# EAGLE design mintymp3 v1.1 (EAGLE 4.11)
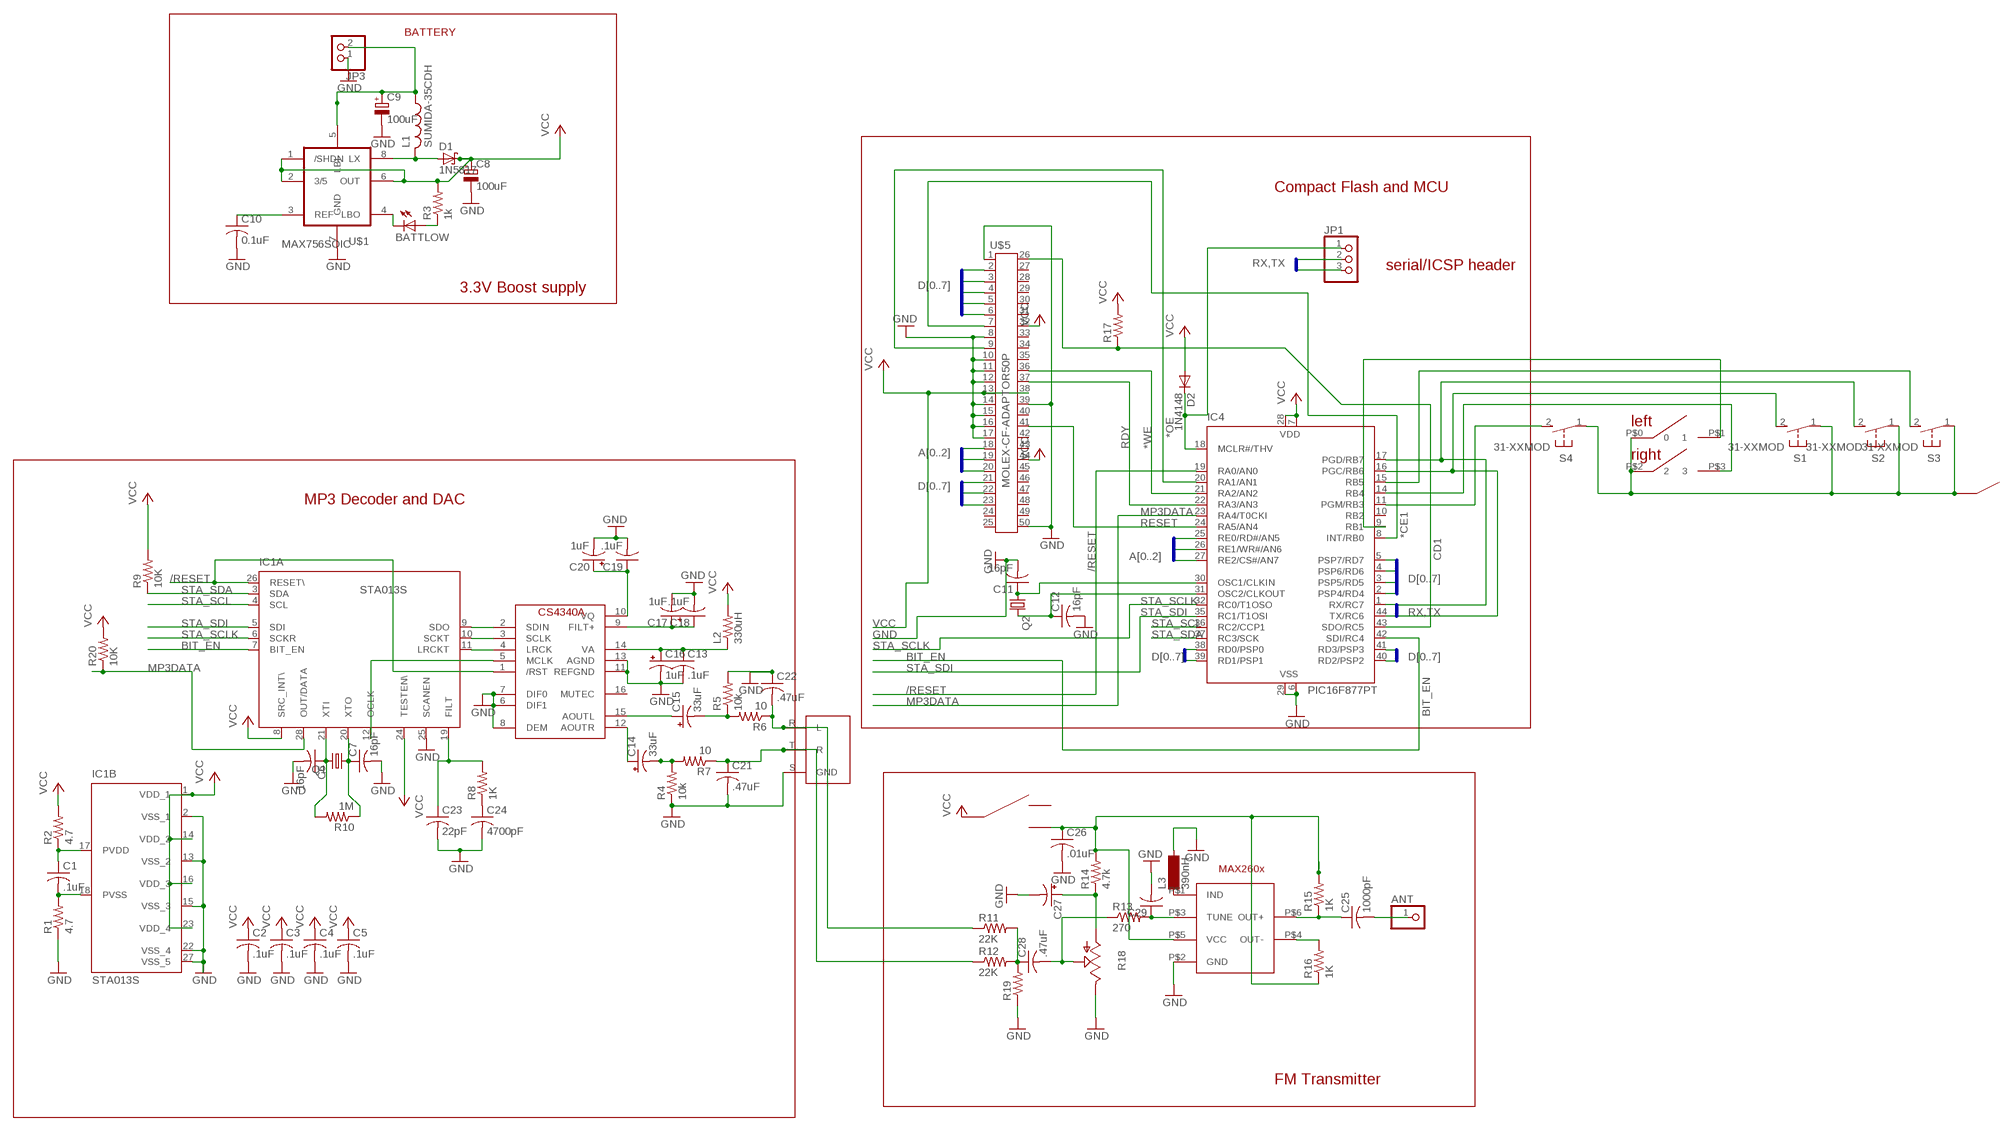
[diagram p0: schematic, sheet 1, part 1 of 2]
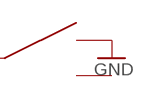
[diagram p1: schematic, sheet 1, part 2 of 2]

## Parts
ANT  PINHD-1X1  [1X01]
BATTLOW  LED3MM  [LED3MM]
C1  .1uF  C-USC1206  [C1206]
C2  .1uF  C-USC1206  [C1206]
C3  .1uF  C-USC1206  [C1206]
C4  .1uF  C-USC1206  [C1206]
C5  .1uF  C-USC1206  [C1206]
C6  16pF  C-USC1206  [C1206]
C7  16pF  C-USC1206  [C1206]
C8  100uF  CPOL-EUD  [PANASONIC_D]
C9  100uF  CPOL-EUD  [PANASONIC_D]
C10  0.1uF  C-USC1206  [C1206]
C11  16pF  C-USC1206  [C1206]
C12  16pF  C-USC1206  [C1206]
C13  .1uF  C-USC1206  [C1206]
C14  33uF  CPOL-USB  [PANASONIC_B]
C15  33uF  CPOL-USB  [PANASONIC_B]
C16  1uF  CPOL-USA  [PANASONIC_A]
C17  1uF  CPOL-USA  [PANASONIC_A]
C18  .1uF  C-USC1206  [C1206]
C19  .1uF  C-USC1206  [C1206]
C20  1uF  CPOL-USA  [PANASONIC_A]
C21  .47uF  C-USC1206  [C1206]
C22  .47uF  C-USC1206  [C1206]
C23  22pF  C-USC1206  [C1206]
C24  4700pF  C-USC1206  [C1206]
C25  1000pF  C-USC1206  [C1206]
C26  .01uF  C-USC1206  [C1206]
C27  CPOL-USB  [PANASONIC_B]
C28  .47uF  C-USC1206  [C1206]
C29  C-USC1206  [C1206]
D1  1N5817  SCHOTTKY-DIODEDO35-7  [DO35-7]
D2  1N4148  [DO35-10]
FM_SWITCH  SLIDE_SW  [SLIDESWITCH]
HEADPHONE  STEREOJACKSMDMOD  [SJ-3523-MODIFIED]
IC1  STA013S  [SO28W]
IC4  PIC16F877PT  [TQFP44]
JP1  PINHD-1X3  [1X03]
JP3  PINHD-1X2  [1X02]
L1  SUMIDA-35CDH  [CDH53]
L2  330uH  R-US_R1210  [R1210]
L3  390nH  SM-1206  [SM-1206]
Q1  CRYTALHC49UP  [HC49UP]
Q2  CRYTALHC49UP  [HC49UP]
R1  4.7  R-US_R1206  [R1206]
R2  4.7  R-US_R1206  [R1206]
R3  1k  R-US_R1206  [R1206]
R4  10k  R-US_R1206  [R1206]
R5  10k  R-US_R1206  [R1206]
R6  10  R-US_R1206  [R1206]
R7  10  R-US_R1206  [R1206]
R8  1K  R-US_R1206  [R1206]
R9  10K  R-US_R1206  [R1206]
R10  1M  R-US_R1206  [R1206]
R11  22K  R-US_R1206  [R1206]
R12  22K  R-US_R1206  [R1206]
R13  270  R-US_R1206  [R1206]
R14  4.7k  R-US_R1206  [R1206]
R15  1K  R-US_R1206  [R1206]
R16  1K  R-US_R1206  [R1206]
R17  R-US_R1206  [R1206]
R18  TRIM_US-ECP10P  [ECP10P]
R19  R-US_R1206  [R1206]
R20  10K  R-US_R1206  [R1206]
S1  31-XXMOD  [B3F-31XX-MODIFIED]
S2  31-XXMOD  [B3F-31XX-MODIFIED]
S3  31-XXMOD  [B3F-31XX-MODIFIED]
S4  31-XXMOD  [B3F-31XX-MODIFIED]
U$1  MAX756SOIC  [SO08]
U$2  SLIDE_SW  [SLIDESWITCH]
U$3  TPC_SWITCH  [TPC_SCAN]
U$4  CS4340A  [SO16]
U$5  MOLEX-CF-ADAPTOR50P  [COMPACTFLASH]
U$9  MAX260X  [SOT23-6]

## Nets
*CE1: IC4.8(INT/RB0) U$5.7
*OE: IC4.20(RA1/AN1) U$5.9
*WE: IC4.21(RA2/AN2) U$5.36
/RESET: IC1.26(A:RESET\) IC4.19(RA0/AN0) U$4.1(/RST)
A0: IC4.25(RE0/RD#/AN5) U$5.20
A1: IC4.26(RE1/WR#/AN6) U$5.19
A2: IC4.27(RE2/CS#/AN7) U$5.18
ANTENNA: ANT.1 C25.2
BIT_EN: IC1.7(A:BIT_EN) IC4.42(SDI/RC4)
BUTTON1: IC4.11(PGM/RB3) S4.2(S)
CD1: IC4.43(SDO/RC5) R17.1 U$5.26
D0: IC4.38(RD0/PSP0) U$5.21
D1: IC4.39(RD1/PSP1) U$5.22
D2: IC4.40(RD2/PSP2) U$5.23
D3: IC4.41(RD3/PSP3) U$5.2
D4: IC4.2(PSP4/RD4) U$5.3
D5: IC4.3(PSP5/RD5) U$5.4
D6: IC4.4(PSP6/RD6) U$5.5
D7: IC4.5(PSP7/RD7) U$5.6
GND: C2.2 C3.2 C4.2 C5.2 C6.2 C7.2 C8.- C9.- C10.2 C11.2 C12.2 C13.2 C16.- C17.- C18.2 C19.2 C20.- C21.2 C22.1 C23.2 C24.2 C26.2 C27.- C29.2 HEADPHONE.S(GND) IC1.2(B:VSS_1) IC1.13(B:VSS_2) IC1.15(B:VSS_3) IC1.22(B:VSS_4) IC1.25(A:SCANEN) IC1.27(B:VSS_5) IC4.6(VSS) IC4.29(VSS) JP3.1 L3.2 R1.1 R4.1 R5.2 R18.E R19.1 U$1.7(GND) U$2.P$1 U$4.6(DIF1) U$4.7(DIF0) U$4.8(DEM) U$4.11(REFGND) U$4.13(AGND) U$5.1 U$5.8 U$5.10 U$5.11 U$5.12 U$5.14 U$5.15 U$5.16 U$5.17 U$5.39 U$5.50 U$9.P$2(GND)
MCLR: D2.C IC4.18(MCLR#/THV) JP1.1
MP3DATA: IC1.28(A:OUT/DATA) IC4.23(RA4/T0CKI) R20.1
N$2: C26.1 FM_SWITCH.P$3 R14.2 R15.2 R16.1 U$9.P$5(VCC)
N$3: C6.1 IC1.21(A:XTI) Q1.2 R10.2
N$4: C7.1 IC1.20(A:XTO) Q1.1 R10.1
N$5: IC4.14(RB4) U$3.P$3
N$6: C1.1 IC1.17(B:PVDD) R2.1
N$7: C1.2 IC1.18(B:PVSS) R1.2
N$8: C9.+ JP3.2 L1.P$1 U$1.5(LBI)
N$9: D1.A L1.P$2 U$1.8(LX)
N$10: IC1.9(A:SDO) U$4.2(SDIN)
N$11: IC1.10(A:SCKT) U$4.3(SCLK)
N$12: IC1.11(A:LRCKT) U$4.4(LRCK)
N$13: IC1.12(A:OCLK) U$4.5(MCLK)
N$14: IC4.9(RB1) U$3.P$1
N$16: IC4.15(RB5) S3.2(S)
N$17: C15.+ U$4.15(AOUTL)
N$18: C10.1 U$1.3(REF)
N$19: BATTLOW.A R3.1
N$20: BATTLOW.K(C) U$1.4(LBO)
N$21: C13.1 C16.+ L2.1 U$4.14(VA)
N$22: C11.1 IC4.30(OSC1/CLKIN) Q2.1
N$23: C12.1 IC4.31(OSC2/CLKOUT) Q2.2
N$24: C14.+ U$4.12(AOUTR)
N$25: C14.- R4.2 R7.2
N$26: C15.- R5.1 R6.2
N$28: C22.2 HEADPHONE.R(L) R6.1 R11.1
N$29: C17.+ C18.1 U$4.9(FILT+)
N$30: C19.1 C20.+ U$4.10(VQ)
N$31: C29.1 R13.2 U$9.P$3(TUNE)
N$32: C24.1 R8.1
N$33: C23.1 IC1.19(A:FILT) R8.2
N$35: C25.1 R15.1 U$9.P$6(OUT+)
N$36: R16.2 U$9.P$4(OUT-)
N$37: C21.1 HEADPHONE.T(R) R7.1 R12.1
N$38: C28.1 R11.2 R12.2 R19.2
N$39: C27.+ R14.1 R18.A
N$40: C28.2 R13.1 R18.S
N$42: L3.1 U$9.P$1(IND)
N$43: S1.1(P) S2.1(P) S3.1(P) S4.1(P) U$2.P$2 U$3.P$0 U$3.P$2
RDY: IC4.22(RA3/AN3) U$5.37
RESET: IC4.24(RA5/AN4) U$5.41
RX: IC4.1(RX/RC7) IC4.17(PGD/RB7) JP1.2 S2.2(S)
STA_SCL: IC1.4(A:SCL) IC4.36(RC2/CCP1)
STA_SCLK: IC1.6(A:SCKR) IC4.32(RC0/T1OSO)
STA_SDA: IC1.3(A:SDA) IC4.37(RC3/SCK) R9.1
STA_SDI: IC1.5(A:SDI) IC4.35(RC1/T1OSI)
TX: IC4.16(PGC/RB6) IC4.44(TX/RC6) JP1.3 S1.2(S)
VCC: C2.1 C3.1 C4.1 C5.1 C8.+ D1.C D2.A FM_SWITCH.P$2 IC1.1(B:VDD_1) IC1.8(A:SRC_INT\) IC1.14(B:VDD_2) IC1.16(B:VDD_3) IC1.23(B:VDD_4) IC1.24(A:TESTEN\) IC4.7(VDD) IC4.28(VDD) L2.2 R2.2 R3.2 R9.2 R17.2 R20.2 U$1.1(/SHDN) U$1.2(3/5) U$1.6(OUT) U$5.13 U$5.32 U$5.38 U$5.44
Unconnected: FM_SWITCH.P$1 IC4.10(RB2) U$2.P$3 U$4.16(MUTEC) U$5.24 U$5.25 U$5.27 U$5.28 U$5.29 U$5.30 U$5.31 U$5.33 U$5.34 U$5.35 U$5.40 U$5.42 U$5.43 U$5.45 U$5.46 U$5.47 U$5.48 U$5.49

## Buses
D[0..7]
A[0..2]
RX,TX

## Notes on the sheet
- BATTERY
- Compact Flash and MCU
- serial/ICSP header
- 3.3V Boost supply
- MP3 Decoder and DAC
- FM Transmitter

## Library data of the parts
ANT = pinhead:PINHD-1X1: PIN HEADER
BATTLOW = led:LED: LED
C1-C7 C10-C13 C18 C19 C21-C26 C28 C29 = rcl:C-US: CAPACITOR, American symbol
C8 C9 = rcl:CPOL-EU: POLARIZED CAPACITOR, European symbol
C14-C17 C20 C27 = rcl:CPOL-US: POLARIZED CAPACITOR, American symbol
D1 = diode:SCHOTTKY-DIODE: Schottky Diode
D2 = diode:1N4148: DIODE
FM_SWITCH U$2 = mp3:SLIDE_SW
HEADPHONE = mp3:STEREOJACK: CUI SJ-3533-N
IC1 = st-microelectronics:STA013S: MP3 AUDIO DECODER
IC4 = microchip:PIC16F87*: MICROCONTROLLER
JP1 = pinhead:PINHD-1X3: PIN HEADER
JP3 = pinhead:PINHD-1X2: PIN HEADER
L1 = mp3:SUMIDA-35CDH
L2 R1-R17 R19 R20 = rcl:R-US_: RESISTOR, American symbol
L3 = inductor-neosid:SM-1206: INDUCTOR
Q1 Q2 = crystal:CRYTAL: CRYSTAL
R18 = pot:TRIM_US-: POTENTIOMETER
S1-S4 = mp3:31-XX: OMRON SWITCH
U$1 = mp3:MAX756
U$3 = mp3:TPC_SWITCH
U$4 = mp3:CS4340A
U$5 = mp3:MOLEX-CF-ADAPTOR
U$9 = mp3:MAX260X

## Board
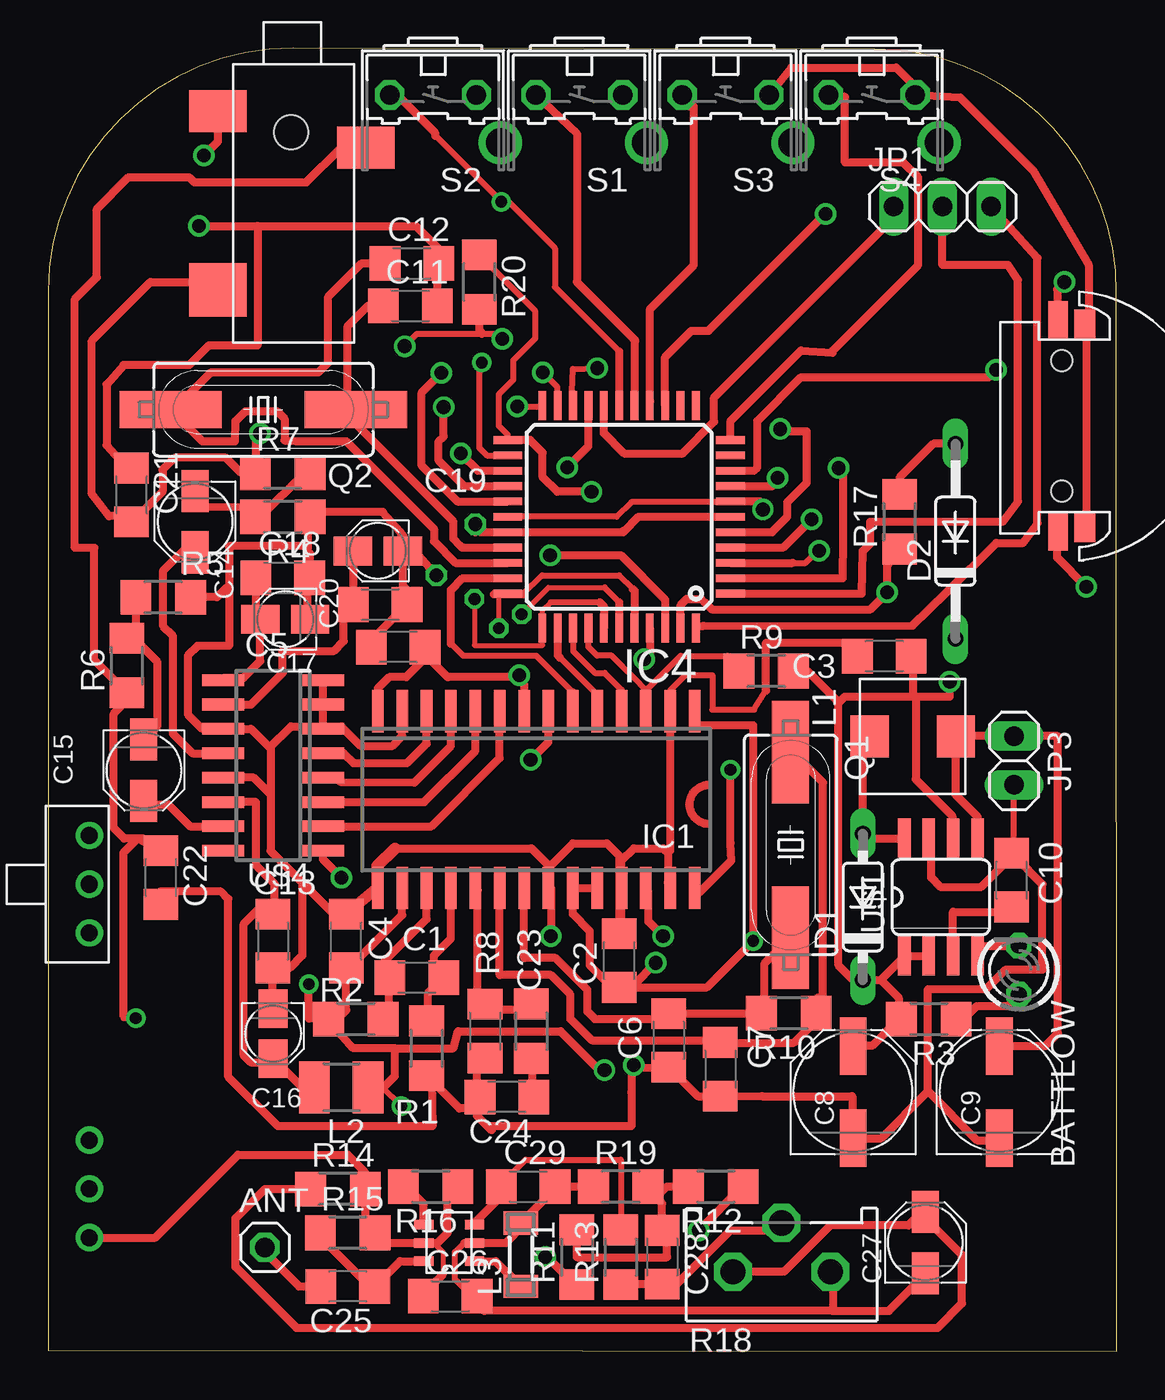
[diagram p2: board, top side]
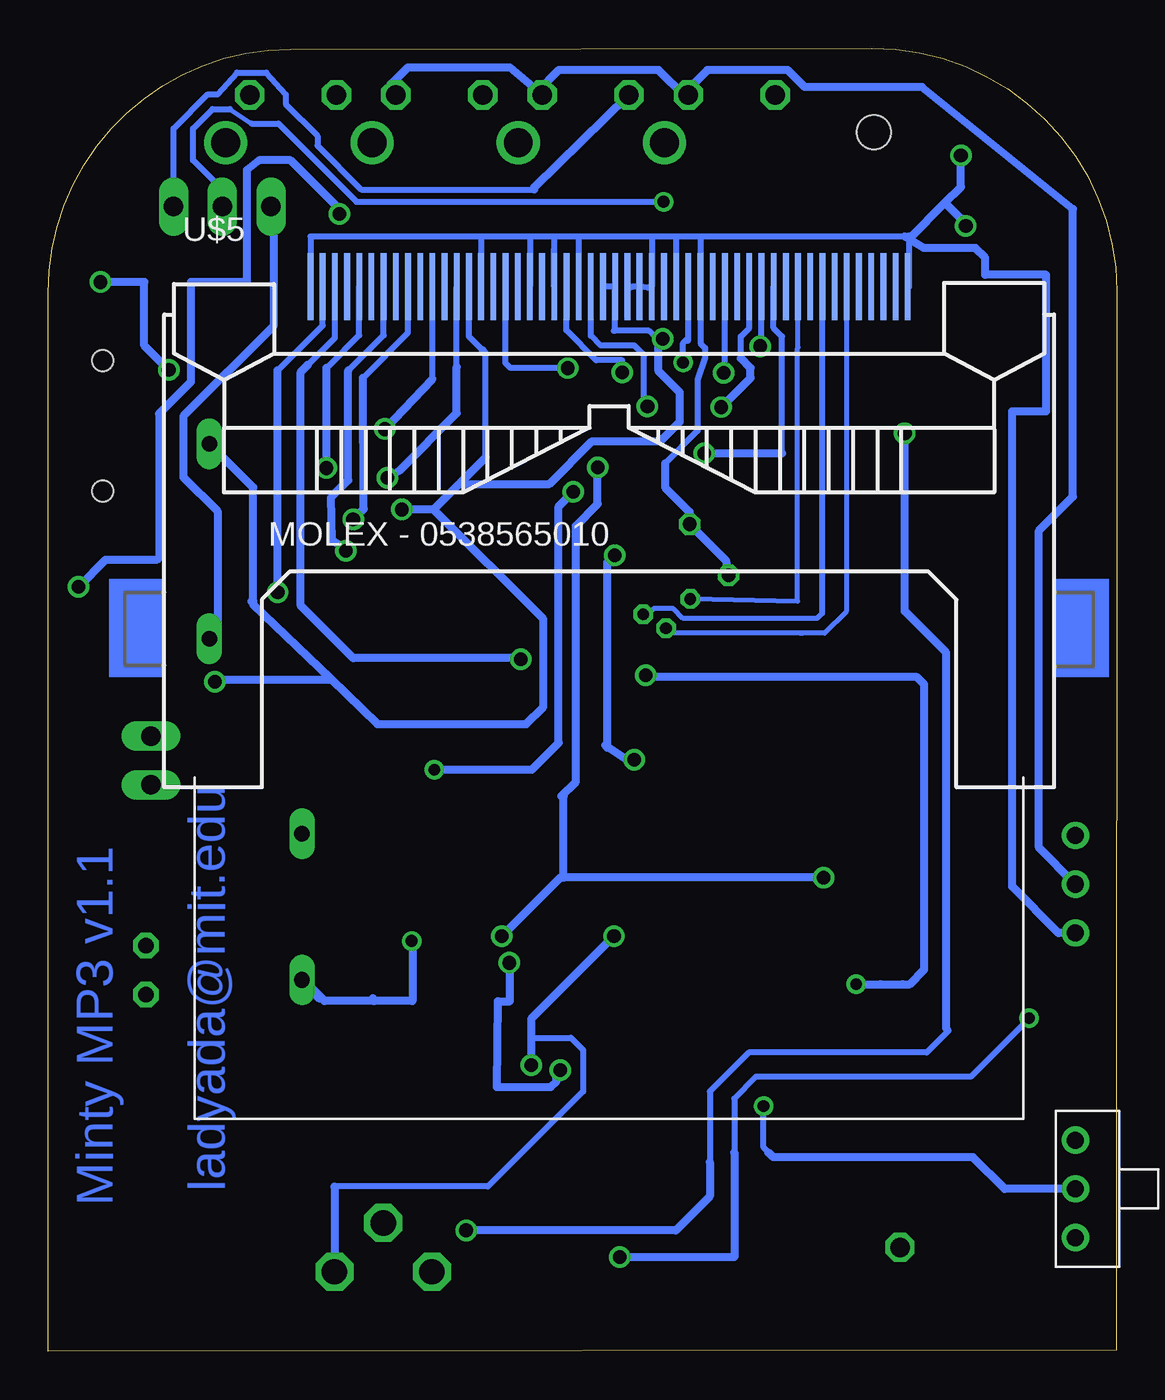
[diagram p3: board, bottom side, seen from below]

Size 55.69 x 67.92 mm. Coordinates in mm from the lower left corner, seen from the top.
Outline: 0.02,0.05 55.69,0 55.67,55.15 arc90 43.06,67.86 12.76,67.91 arc90 0,55.24 0.02,0.05
Copper layers (1*16): Top 0.035mm / dielectric 1.5mm / Bottom 0.035mm
Design rules "default": minimum track width 10mil, minimum drill 24mil, track to track 10mil, track to pad 10mil, pad to pad 10mil, via to via 10mil, smd to smd 8mil, copper to edge 20mil, drill to drill 8mil, minimum pad ring 10mil, minimum via ring 8mil, stop-mask expansion 4mil, vias tented up to drill 0mil, thermal gap 10mil

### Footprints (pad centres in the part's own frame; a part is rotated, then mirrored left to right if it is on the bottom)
1X01 = drill 1.016 octagon: 1 0,0
LED3MM = drill 0.813 octagon: A -1.27,0; K 1.27,0
C1206 = smd 1.6 x 1.8: 1 -1.4,0; 2 1.4,0
PANASONIC_D = smd 3 x 1.4: + 2.4,0; - -2.4,0
PANASONIC_B = smd 2.2 x 1.4: + 1.6,0; - -1.6,0
PANASONIC_A = smd 2 x 1.5: + 1.3,0; - -1.3,0
DO35-7 = drill 0.813 long: A 3.81,0; C -3.81,0
DO35-10 = drill 0.813 long: A 5.08,0; C -5.08,0
SLIDESWITCH = drill 0.889 pad 1.422 round: P$1 -2.54,1.016; P$2 0,1.016; P$3 2.54,1.016
SJ-3523-MODIFIED = smd 2.2 x 3: R -3.27,3.82; S -5.17,-3.88 | smd 2.8 x 3: T 4.13,-3.88 | hole 1.778: -4.07,-0.08
SO28W = smd 0.6 x 2.2: 1 -8.255,-4.6; 2 -6.985,-4.6; 3 -5.715,-4.6; 4 -4.445,-4.6; 5 -3.175,-4.6; 6 -1.905,-4.6; 7 -0.635,-4.6; 8 0.635,-4.6; 9 1.905,-4.6; 10 3.175,-4.6; 11 4.445,-4.6; 12 5.715,-4.6; 13 6.985,-4.6; 14 8.255,-4.6; 15 8.255,4.6; 16 6.985,4.6; 17 5.715,4.6; 18 4.445,4.6; 19 3.175,4.6; 20 1.905,4.6; 21 0.635,4.6; 22 -0.635,4.6; 23 -1.905,4.6; 24 -3.175,4.6; 25 -4.445,4.6; 26 -5.715,4.6; 27 -6.985,4.6; 28 -8.255,4.6
TQFP44 = smd 1.5 x 0.4: 1 -5.8,4; 2 -5.8,3.2; 3 -5.8,2.4; 4 -5.8,1.6; 5 -5.8,0.8; 6 -5.8,0; 7 -5.8,-0.8; 8 -5.8,-1.6; 9 -5.8,-2.4; 10 -5.8,-3.2; 11 -5.8,-4; 23 5.8,-4; 24 5.8,-3.2; 25 5.8,-2.4; 26 5.8,-1.6; 27 5.8,-0.8; 28 5.8,0; 29 5.8,0.8; 30 5.8,1.6; 31 5.8,2.4; 32 5.8,3.2; 33 5.8,4 | smd 0.4 x 1.5: 12 -4,-5.8; 13 -3.2,-5.8; 14 -2.4,-5.8; 15 -1.6,-5.8; 16 -0.8,-5.8; 17 0,-5.8; 18 0.8,-5.8; 19 1.6,-5.8; 20 2.4,-5.8; 21 3.2,-5.8; 22 4,-5.8; 34 4,5.8; 35 3.2,5.8; 36 2.4,5.8; 37 1.6,5.8; 38 0.8,5.8; 39 0,5.8; 40 -0.8,5.8; 41 -1.6,5.8; 42 -2.4,5.8; 43 -3.2,5.8; 44 -4,5.8
1X03 = drill 1.016 long: 1 -2.54,0; 2 0,0; 3 2.54,0
1X02 = drill 1.016 long: 1 -1.27,0; 2 1.27,0
CDH53 = smd 2.2 x 2: P$1 1,1; P$2 1,5.5
R1210 = smd 1.6 x 2.7: 1 -1.4,0; 2 1.4,0
SM-1206 = smd 1.2 x 1.8: 1 -1.65,0; 2 1.65,0
HC49UP = smd 5.334 x 1.93: 1 -4.826,0; 2 4.826,0
R1206 = smd 1.6 x 1.803: 1 -1.422,0; 2 1.422,0
ECP10P = drill 1.321 octagon: A -2.54,0; E 2.54,0; S 0,2.54
B3F-31XX-MODIFIED = drill 1.016 octagon: 1 -2.261,-1.245; 2 2.261,-1.245 | drill 1.499 pad 2.159 round: 3 -3.505,1.245
SO08 = smd 0.66 x 2.032: 1 -1.905,-3.073; 2 -0.635,-3.073; 3 0.635,-3.073; 4 1.905,-3.073; 5 1.905,3.073; 6 0.635,3.073; 7 -0.635,3.073; 8 -1.905,3.073
TPC_SCAN = smd 1.5 x 1.1: P$0 -5.3,1.2; P$2 5.3,1.2 | smd 2 x 1: P$1 -5.5,-0.2; P$3 5.5,-0.2 | hole 1.1: -3.4,0; 3.4,0
SO16 = smd 0.6 x 2.2: 1 -4.445,-2.6; 2 -3.175,-2.6; 3 -1.905,-2.6; 4 -0.635,-2.6; 5 0.635,-2.6; 6 1.905,-2.6; 7 3.175,-2.6; 8 4.445,-2.6; 9 4.445,2.6; 10 3.175,2.6; 11 1.905,2.6; 12 0.635,2.6; 13 -0.635,2.6; 14 -1.905,2.6; 15 -3.175,2.6; 16 -4.445,2.6
COMPACTFLASH = smd 0.3 x 3.5: 1 -16.828,10.335; 2 -15.557,10.335; 3 -14.287,10.335; 4 -13.018,10.335; 5 -11.748,10.335; 6 -10.477,10.335; 7 -9.207,10.335; 8 -7.938,10.335; 9 -6.668,10.335; 10 -5.397,10.335; 11 -4.128,10.335; 12 -2.857,10.335; 13 -1.587,10.335; 14 -0.318,10.335; 15 0.953,10.335; 16 2.223,10.335; 17 3.493,10.335; 18 4.763,10.335; 19 6.032,10.335; 20 7.303,10.335; 21 8.572,10.335; 22 9.842,10.335; 23 11.113,10.335; 24 12.383,10.335; 25 13.652,10.335; 26 -16.192,10.335; 27 -14.922,10.335; 28 -13.652,10.335; 29 -12.383,10.335; 30 -11.113,10.335; 31 -9.842,10.335; 32 -8.572,10.335; 33 -7.303,10.335; 34 -6.032,10.335; 35 -4.763,10.335; 36 -3.493,10.335; 37 -2.223,10.335; 38 -0.953,10.335; 39 0.318,10.335; 40 1.587,10.335; 41 2.857,10.335; 42 4.128,10.335; 43 5.397,10.335; 44 6.668,10.335; 45 7.938,10.335; 46 9.207,10.335; 47 10.477,10.335; 48 11.748,10.335; 49 13.018,10.335; 50 14.287,10.335
SOT23-6 = smd 0.5 x 1: P$1 0.3,0.5; P$2 1.25,0.5; P$3 2.2,0.5; P$4 2.2,3.15; P$5 1.25,3.15; P$6 0.3,3.15

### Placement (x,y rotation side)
ANT  11.3,5.42 0 top
BATTLOW  50.59,19.87 90 top
C1  19.22,19.49 0 top
C2  29.76,20.38 90 top
C3  43.58,36.22 180 top
C4  15.54,21.39 90 top
C5  18.25,36.7 180 top
C6  32.35,16.21 270 top
C7  35.03,14.71 270 top
C8  41.95,13.52 90 top
C9  49.57,13.52 90 top
C10  50.21,24.57 90 top
C11  18.88,54.48 0 top
C12  18.96,56.7 0 top
C13  11.73,21.39 270 top
C14  7.66,43.23 270 top
C15  4.99,30.28 270 top
C16  11.73,16.57 270 top
C17  12.36,38.16 180 top
C18  12.23,40.31 0 top
C19  17.31,38.92 0 top
C20  17.19,41.71 180 top
C21  4.36,44.63 90 top
C22  5.88,24.69 90 top
C23  22.77,16.69 270 top
C24  23.92,13.26 180 top
C25  15.62,3.39 180 top
C26  20.95,2.88 0 top
C27  45.72,5.68 90 top
C28  32,4.92 270 top
C29  25.02,8.6 0 top
D1  42.46,23.17 90 top
D2  47.29,42.22 90 top
FM_SWITCH  3.17,8.47 270 bottom
HEADPHONE  12.74,59.45 270 top
IC1  25.44,28.76 180 top
IC4  29.76,43.49 180 top
JP1  46.61,59.65 0 top
JP3  50.33,30.79 90 top
L1  48.3,31.04 90 top
L2  15.28,13.77 0 top
L3  24.64,5.04 90 top
Q1  38.7,26.4 270 top
Q2  11.22,49.08 180 top
R1  19.73,15.8 90 top
R2  16.04,17.33 180 top
R3  45.89,17.33 180 top
R4  12.23,43.49 180 top
R5  6.01,39.3 0 top
R6  4.11,35.74 90 top
R7  12.23,45.77 0 top
R8  25.19,16.69 90 top
R9  37.42,35.46 0 top
R10  38.6,17.64 180 top
R11  27.56,4.92 90 top
R12  34.8,8.6 180 top
R13  29.84,4.92 90 top
R14  15.11,8.47 0 top
R15  15.62,6.19 0 top
R16  19.94,8.6 180 top
R17  44.36,43.23 90 top
R18  38.23,4.15 0 top
R19  29.84,8.6 0 top
R20  22.48,55.72 270 top
S1  27.69,64.22 180 top
S2  20.07,64.22 180 top
S3  35.31,64.22 180 top
S4  42.93,64.22 180 top
U$1  46.52,23.68 0 top
U$2  3.17,24.35 90 top
U$3  52.83,48.22 270 top
U$4  11.73,30.54 90 top
U$5  25.19,45.14 0 bottom
U$9  22.73,4.41 90 top

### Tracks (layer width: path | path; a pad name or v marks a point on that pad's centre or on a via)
*CE1  (via drill 0.71)
  Top 0.406: IC4.8 37.77,45.1 38.14,45.47 v38.01,45.52
  Bottom 0.305: 34.4,51.3 U$5.7
  Bottom 0.406: v38.01,45.52 37.37,45.9 34.4,48.88 34.4,51.3
*OE  (via drill 0.71)
  Top 0.305: v28.62,51.24 27.35,51.19 27.3,50 27.36,49.95 IC4.20
  Bottom 0.305: v28.62,51.24 31.59,51.24 31.86,51.5 U$5.9
*WE  (via drill 0.71)
  Top 0.305: v25.78,51.02 26.54,50.26 26.54,49.37 26.56,49.35 IC4.21
  Bottom 0.305: U$5.36 28.68,53.2 27.13,51.65 25.78,51.65 v25.78,51.02
/RESET  (via drill 0.71)
  Top 0.406: v32.05,21.64 31.28,22.41 31.28,23.93 31.16,23.93 | 31.16,23.93 31.03,23.93 | 31.16,23.93 IC1.26 | U$4.1 14.33,25.65 v15.28,24.69 | IC4.19 28.16,47.17 v27.05,46.06
  Bottom 0.406: v15.28,24.69 28.83,24.69 | 28.83,24.69 29,24.69 v32.05,21.64 30.74,22.95 | v27.05,46.06 27.05,44.16 28.19,43.02 28.19,29.68 28.96,28.92 28.83,28.92 28.83,24.69
A0  (via drill 0.71)
  Top 0.406: IC4.25 22.41,45.89 v21.5,46.79
  Bottom 0.305: U$5.20 17.89,53.33 17.44,52.89 17.44,46.79
  Bottom 0.406: 17.44,46.79 v21.5,46.79
A1  (via drill 0.71)
  Top 0.406: v20.62,49.2 20.62,47.68 20.36,47.43 20.36,46.41 21.68,45.09 IC4.26
  Bottom 0.305: U$5.19 19.16,53.33 19.6,52.89 19.6,51.74
  Bottom 0.406: 19.6,51.74 19.09,51.24 19.09,50.73 v20.62,49.2
A2  (via drill 0.71)
  Top 0.406: v20.49,50.98 19.47,49.97 19.47,46.16 21.34,44.29 IC4.27
  Bottom 0.305: 20.43,51.17 U$5.18
  Bottom 0.406: v20.49,50.98 20.43,51.17
ANTENNA
  Top 0.406: ANT.1 11.3,5.17 13.08,3.39 C25.2
BIT_EN  (via drill 0.71)
  Top 0.406: IC4.42 32.16,39.18 29.84,41.49 v26.16,41.49 | IC1.7 26.08,31.76 v25.15,30.82
  Bottom 0.406: v26.16,41.49 26.54,41.11 26.54,31.46 26.67,31.59 25.53,30.82 v25.15,30.82
BUTTON1
  Top 0.406: IC4.11 35.56,48.48 39.24,52.16 40.89,52.03 40.89,52.16 45.34,56.61 45.34,61.18 44.58,61.94 41.53,61.94 41.53,65.37 41.3,65.37 S4.2
CD1  (via drill 0.71)
  Top 0.406: 32.96,37.62 IC4.43 32.96,38.89 33.27,39.21 34.04,39.21 34.2,39.04 34.59,38.66 42.84,38.66 v43.73,39.55 43.73,40.95 44.34,41.81 R17.1
  Bottom 0.305: U$5.26 41.38,53.46 43.73,51.11
  Bottom 0.406: v43.73,39.55 43.73,51.11
D0  (via drill 0.61)
  Top 0.254: 26.2,39.04 25.78,38.62 25.78,36.79 22.22,36.79 v22.22,39.21
  Top 0.305: 26.2,39.04 28.74,39.04
  Top 0.406: IC4.38 28.96,38.82 28.74,39.04
  Bottom 0.254: v22.22,39.21 16.64,39.08 16.64,52.29 16.61,52.31 U$5.21
D1  (via drill 0.61)
  Top 0.254: 29,39.81 26.08,39.81 v24.68,38.41
  Top 0.305: 29,39.81 29.76,39.04
  Top 0.406: 29.76,39.04 IC4.39
  Bottom 0.254: 15.35,38.47 15.37,38.45 15.37,38.44 15.62,38.19 22.61,38.19 23.11,38.7 24.14,38.7 24.39,38.44 v24.68,38.41
  Bottom 0.305: 15.35,55.49 U$5.22 15.35,38.47
D2  (via drill 0.61)
  Top 0.254: 23.24,39.46 23.49,39.33 v23.49,37.68
  Top 0.305: 30.52,39.68 30.48,39.72 29.76,40.44 25.75,40.44 24.76,39.46
  Top 0.406: 30.48,39.72 30.48,39.71 30.56,39.63 IC4.40 | 23.24,39.46 24.76,39.46
  Bottom 0.254: v23.49,37.68 23.49,37.43 16.51,37.43 | 16.51,37.43 16.38,37.43 | U$5.23 14.07,38.59 15.24,37.43 16.51,37.43
D3  (via drill 0.71)
  Top 0.406: v31.06,36.07 31.06,36.11 31.36,36.4 IC4.41
  Bottom 0.305: 42.21,51.36 42.17,51.4 40.74,52.82 U$5.2
  Bottom 0.406: v31.06,36.07 v31.08,36.07 31.11,36.03 31.21,36.12 39.79,36.12 42.52,38.85 42.52,51.04 42.16,51.4 42.17,51.4
D4  (via drill 0.71)
  Top 0.406: IC4.2 41.42,40.29 41.44,42.35 41.44,45.77 v41.19,46.03
  Bottom 0.305: 41.19,51.24 41.06,51.36 39.48,52.94 U$5.3
  Bottom 0.406: v41.19,46.03 41.19,51.24
D5  (via drill 0.71)
  Top 0.305: v40.17,41.71 40.13,41.75 39.47,41.09 38.79,41.09
  Top 0.406: IC4.3 38.79,41.09
  Bottom 0.305: U$5.4 38.2,52.95 40.05,51.11
  Bottom 0.406: v40.17,41.71 40.17,41.79 40.89,42.25 40.94,44.51 40.05,45.39 40.05,51.11
D6  (via drill 0.71)
  Top 0.406: IC4.4 38.32,41.89 v39.79,43.36
  Bottom 0.305: U$5.5 36.94,53.08 39.28,50.73
  Bottom 0.406: v39.79,43.36 39.54,43.61 39.24,43.91 39.28,50.73
D7  (via drill 0.71)
  Top 0.406: IC4.5 37.72,42.69 38.52,43.49 38.52,44.25 39.54,45.27 39.54,47.93 38.26,47.93 38.13,48.06 | 38.13,48.06 38.1,48.1 | 38.13,48.06 v38.14,48.06
  Bottom 0.305: 35.66,50.66 U$5.6
  Bottom 0.406: v38.14,48.06 35.66,50.66
GND  (via drill 0.71)
  Top 0.305: 32.3,25.96 32.43,26.09 | IC1.2 32.43,34.45 33.21,35.24 34.61,35.24 34.61,33.44 36.79,33.44 37.41,34.44 | 21.7,5.66 21.21,5.17 21.21,3.77 22.1,2.88 | 50.18,25.87 50.17,25.87 50.16,25.87 50.33,26.04 JP3.1
  Top 0.406: IC1.27 32.43,24.31 32.3,24.44 32.3,25.96 32.05,26.22 30.52,26.22 29.89,25.58 IC1.25 29.89,22.03 29.76,21.9 C2.2 29.76,25.84 29.12,26.47 27.35,26.47 26.08,25.2 | 26.08,25.2 26.08,25.33 25.19,26.22 18.08,26.22 | C19.2 18.33,38.54 | 30.4,14.78 C6.2 33.86,13.3 35.05,13.3 | v30.52,14.91 30.4,14.78 | v26.2,21.64 26.2,24.19 26.08,24.31 | 22.9,11.74 30.39,11.74 30.4,13.52 30.4,14.78 | 46.02,26.73 45.99,26.75 U$1.7 | 46.02,26.73 45.89,26.6 | 46.02,26.73 46.02,24.69 46.52,24.19 48.61,24.19 50.13,25.71 50.18,25.87 C10.2 50.45,25.71 51.82,24.35 51.82,19.9 49.91,19.9 48.89,18.89 45.85,18.89 45.85,13.57 | 11.6,29.01 11.6,31.42 11.56,31.46 | 13.25,24.44 13.25,20.63 12.61,19.99 C13.2 11.68,19.95 11.68,17.91 C16.- | 13.25,24.44 11.6,26.09 11.6,29.01 | 14.27,32.57 14.33,32.51 U$4.6 | 14.27,32.57 14.33,32.63 U$4.7 14.33,33.78 14.27,33.84 14.33,33.9 U$4.8 | 26.08,25.2 26.08,24.31 | 26.08,24.31 IC1.22 | 11.56,31.46 10.58,32.44 9.19,32.44 | 9.19,32.44 U$4.11 | 9.19,32.44 8.04,32.44 7.28,33.2 7.28,36.25 7.79,36.76 9.44,36.76 9.44,39.81 | 11.6,29.01 10.71,29.9 U$4.13 | 30.01,42.72 29.98,42.69 | 30.01,42.72 30.78,43.49 IC4.6 | 32.43,26.09 IC1.2 | v22.27,43.11 22.27,42.89 | 22.27,42.89 22.27,42.69 | IC1.13 18.46,33.33 | IC1.13 18.46,33.46 | 14.27,32.57 15.28,32.57 16.3,31.55 17.95,31.55 18.46,32.06 IC1.13 | 13.53,41.48 13.63,41.59 C18.2 | 13.53,43.74 13.53,41.97 | 13.53,41.97 13.53,41.48 | 13.53,43.74 R4.1 | 13.53,41.48 13.5,41.46 13.5,38.79 13.53,38.82 C17.- | 18.33,38.54 19.22,39.17 18.49,39.9 C20.- 18.36,42.7 | 18.36,42.7 17.44,43.74 13.53,43.74 | 18.36,42.7 18.52,42.47 | 9.44,39.81 9.44,41.97 13.53,41.97 | 18.36,42.7 18.61,42.32 v20.23,40.44
  Top 0.406: 9.44,39.81 9.31,39.81 8.8,39.3 R5.2 | 37.41,34.44 37.41,36.94 41.38,36.94 42.16,36.16 42.18,36.17 C3.2 42.12,36.22 | 35.05,13.3 | 35.05,13.3 C7.2 37.21,13.3 41.91,13.3 41.93,11.12 C8.- 43.41,11.12 45.85,13.55 45.85,13.57 | 22.35,12.79 22.3,12.79 C24.2 22.22,12.72 22.22,12.66 21.44,12.66 19.99,14.11 | C23.2 22.35,14.49 22.35,12.79 | 22.9,11.74 22.35,12.29 22.35,12.79 | 19.99,14.11 R1.1 | C9.- 49.66,11.03 49.66,11.01 48.41,11.01 45.85,13.57 | 11.56,31.46 | 14.27,32.57 12.66,32.57 11.56,31.46 | C22.1 5.85,23.97 9.02,23.97 9.4,23.59 9.4,14.32 11.98,11.74 20.03,11.74 19.99,14.11 | C4.2 15.5,22.82 14.87,22.82 13.25,24.44 | C5.2 16.94,36.79 17.02,36.79 17.02,37.22 18.33,38.54 | 21.7,5.66 U$9.P$2 23.86,5.66 24.76,6.57 L3.2 26.54,8.6 | 22.1,2.88 C26.2 22.35,2.5 22.73,2.12 40.89,2.12 | 26.54,8.6 C29.2 | 26.54,8.6 R19.1 | C27.- 45.72,4.03 43.81,2.12 40.89,2.12 | 40.89,2.12 40.89,4.03 R18.E | HEADPHONE.S 8.14,64.62 | HEADPHONE.S 9.23,64.99 | HEADPHONE.S 8.86,63.05 v8.13,62.32 | 20.45,56.61 C12.2 | C11.2 20.28,56.44 20.45,56.61 | 20.45,56.61 20.45,57.37 19.18,58.64 10.92,58.64 | C21.2 4.1,46.03 3.05,47.21 3.05,50.38 3.94,51.4 7.37,51.4 8.38,52.41 10.92,52.41 10.92,58.64 | 30.01,42.72 29.97,42.76 29.9,42.69 IC4.29 22.55,42.69 22.35,42.89 22.27,42.89 | 22.9,11.74 23.11,11.53 | v7.87,58.64 10.92,58.64
  Top 0.61: C4.2 17.09,24.09 17.14,24.09 17.14,24.12 IC1.15 17.14,24.2 17.14,25.29 18.08,26.22
  Bottom 0.305: 22.96,58.09 U$5.16 | 21.7,58.09 22.96,58.09 | 21.7,58.09 U$5.17 21.7,52.52 21.46,52.29 21.46,51.78 21.84,50.64 21.84,47.97 23.53,46.28 23.54,46.28 | 33.12,58.09 U$5.8 | 30.59,58.09 U$5.10 | 30.59,58.09 33.12,58.09 | U$5.1 42.02,58.09 33.12,58.09 | U$5.11 29.32,57.46 | 22.96,58.09 22.9,58.09 | U$5.14 25.44,55.43 arc22 U$5.39 24.43,55.43 U$5.15 24.23,58.09 24.3,58.09 | U$5.11 29.32,57.4 | 29.32,58.09 U$5.11 | 22.96,58.09 24.3,58.09 | 24.3,58.09 28.11,58.09 | 28.11,58.09 29.32,58.09 | 29.32,58.09 30.59,58.09 | U$5.12 28.05,58.09 28.11,58.09 | 11.05,58.09 21.7,58.09 | U$5.50 10.84,55.48 10.84,58 10.84,58.09 | 40.77,8.6 32.77,8.6 27.81,13.55 27.81,15.71 28.45,16.35 30.35,16.35 30.48,16.22 30.52,16.22
  Bottom 0.406: v30.52,14.91 30.52,16.22 30.52,17.33 v26.2,21.64 | 23.54,46.28 23.54,45.01 22.27,43.74 v22.27,43.11 20.36,41.2 v20.23,40.44 | 40.77,8.6 R18.E | 10.84,58.09 11.05,58.09 10.07,57.49 7.37,57.49 6.86,56.99 6.86,56.1 3.68,56.1 3.68,48.98 5.46,48.98 5.46,24.22 3.05,21.81 U$2.P$1 | 10.84,58 10.79,58 8.95,59.84 | v8.13,62.32 8.13,60.67 8.95,59.84 | v7.87,58.64 7.87,58.76 8.95,59.84
MCLR
  Top 0.406: IC4.18 28.96,47.84 30.01,46.79 33.06,46.79 34.71,48.44 34.71,49.71 43.89,58.89 44.07,58.89 JP1.1
  Bottom 0.406: D2.C 46.86,37.77 46.86,43.78 48.64,45.56 48.64,48.73 43.94,53.43 43.94,59.53 44.07,59.53 44.2,59.65 JP1.1
MP3DATA  (via drill 0.61, 0.71)
  Top 0.305: IC4.23 23.96,47.76 23.49,48.22 23.49,49.87 24.26,50.64 24.26,51.65 25.4,52.8 25.4,54.19 22.48,57.11 R20.1
  Top 0.406: IC1.28 33.7,23.93 33.95,23.93 35.6,25.58 35.56,26.47 v35.56,30.32 | IC4.23 25.12,47.49 25.78,46.83 25.78,45.56 26.54,44.79 v28.32,44.79
  Bottom 0.406: v28.32,44.79 29.08,44.03 29.08,31.71 30.48,30.32 v35.56,30.32
N$2
  Top 0.254: 20.09,5.66 20.57,5.17 20.57,4.03
  Top 0.406: R16.1 21.46,8.6 20.83,7.96 20.83,6.19 20.3,5.66 U$9.P$5 | 17.02,6.19 16.53,6.67 R14.2 16.53,8.57 16.51,8.6 16.51,9.36 15.62,10.25 9.91,10.25 5.59,5.93 FM_SWITCH.P$3 | 17.02,6.19 R15.2 | U$9.P$5 17.55,5.66 17.02,6.19 | U$9.P$5 20.09,5.66 | C26.1 19.55,3.01 20.57,4.03
N$3
  Top 0.406: IC1.21 24.81,20.5 26.46,20.5 28.11,18.85 28.11,17.71 28.49,17.33 32.21,17.33 32.21,17.71 | 32.21,17.71 32.21,17.74 | 32.21,17.71 C6.1 37.31,17.61 37.21,17.84 | 37.21,17.84 37.21,17.94 | 37.21,17.84 R10.2 37.2,17.62 37.34,17.62 37.34,20.21 Q1.2
N$4
  Top 0.406: IC1.20 23.54,19.61 26.2,19.61 27.22,18.6 27.22,17.33 28.34,16.21 34.93,16.21 C7.1 | Q1.1 38.7,31.34 40.39,29.65 40.39,18.44 | 40.17,18.34 40.17,18.44 40.39,18.44 | 40.11,17.36 40.11,17.24 | 40.11,17.36 40.11,17.84 R10.1 40.02,18.35 40.11,18.44 40.39,18.44 | C7.1 35.05,16.09 38.86,16.09 40.13,17.36 40.11,17.36 | C7.1
N$5  (via drill 0.71)
  Top 0.406: v40.51,59.27 34.42,53.18 33.53,53.18 32.16,51.81 IC4.14 | U$3.P$3 52.58,42.67 52.58,41.37 v54.1,39.84
  Bottom 0.406: v40.51,59.27 40.51,59.53 43.05,62.07 44.7,62.07 45.34,61.56 45.34,55.72 48.26,55.72 48.26,50.51 49.91,48.86 49.91,41.37 50.04,41.24 52.7,41.24 v54.1,39.84
N$6
  Top 0.406: IC1.17 19.73,22.53 17.53,20.33 17.53,19.14 17.66,19.14 C1.1 17.78,19.02 17.78,17.13 R2.1
N$7
  Top 0.305: 20.57,19.39 20.55,19.42 20.36,19.61
  Top 0.406: IC1.18 21,21.52 20.11,20.63 20.11,19.87 20.36,19.61 20.24,19.49 | R1.2 19.81,17.31 19.81,18.68 20.55,19.42 C1.2
N$8
  Top 0.406: 48.45,26.73 U$1.5 48.43,27.87 47.29,29.01 47.29,31.8 47.3,31.82 L1.P$1 47.29,32.06 | C9.+ 51.97,15.92 52.62,16.57 52.62,32.06 JP3.2 47.29,32.06 | 47.29,32.06 47.16,32.19
N$9
  Top 0.406: U$1.8 44.59,26.73 42.71,26.73 D1.A | D1.A 42.46,26.22 | L1.P$2 42.46,31.7 D1.A
N$10
  Top 0.406: U$4.2 19.98,27.36 23.54,30.92 IC1.9
N$11
  Top 0.406: IC1.10 22.27,31.3 19.6,28.63 U$4.3
N$12
  Top 0.406: U$4.4 15.02,29.9 15.24,29.68 19.09,29.65 21,31.55 IC1.11
N$13
  Top 0.406: U$4.5 15.41,31.17 15.92,30.66 18.71,30.66 19.73,31.68 IC1.12
N$14  (via drill 0.71)
  Top 0.406: v49.4,51.14 49.02,50.76 39.24,50.76 36.96,48.48 36.96,46.06 36.78,45.89 IC4.9 | U$3.P$1 52.58,53.78 52.58,55.34 v52.96,55.72
  Bottom 0.406: v49.4,51.14 50.67,52.41 50.67,55.72 v52.96,55.72
N$16
  Top 0.406: IC4.15 31.36,49.48 31.37,49.49 31.37,54.32 33.65,56.61 33.65,64.86 33.4,64.86 33.4,65.34 S3.2
N$17
  Top 0.406: U$4.15 7.41,27.36 6.26,28.5 5.12,28.5 4.96,28.47 C15.+
N$18
  Top 0.406: U$1.3 47.16,22.92 50.84,22.92 C10.1
N$19
  Top 0.406: R3.1 47.84,17.45 48.39,18 50.04,18 50.59,18.55 BATTLOW.A
N$20
  Top 0.406: U$1.4 48.39,20.6 48.39,21.14 BATTLOW.K
N$21
  Top 0.406: 11.81,22.92 10.96,23.04 10.2,22.28 10.2,15.42 10.55,15.08 11.68,15.08 11.68,15.22 C16.+ 13.18,13.81 13.92,13.81 | 11.81,22.92 11.85,22.92 | 11.85,22.92 C13.1 | U$4.14 10.84,28.63 10.84,25.33 11.81,24.35 11.81,22.92 | 11.85,22.92 11.76,23.2 | 13.92,13.81 13.97,13.81 | 13.92,13.81 L2.1
N$22
  Top 0.406: Q2.1 16.3,49.08 | Q2.1 16.04,48.31 21.12,43.23 21.12,42.35 21.47,42 | 21.47,42 21.5,41.97 | 21.47,42 21.46,42 21.59,41.87 21.61,41.89 IC4.30 | Q2.1 16.04,49.2 15.62,49.62 15.62,53.43 16.67,54.48 C11.1
N$23
  Top 0.406: 6.26,49.08 Q2.2 6.48,48.99 | IC4.31 21.24,41.09 20.11,42.22 20.11,42.85 15.54,47.43 12.95,47.43 12.32,47.46 12.32,48.6 11.94,48.98 10.29,48.98 9.78,48.48 9.74,47.43 8.04,47.43 6.48,48.99 | 6.48,48.99 8.51,51.02 14.1,51.02 14.6,51.52 14.6,54.95 16.35,56.7 C12.1
N$24
  Top 0.406: 9.06,31.17 U$4.12 9.13,31.19 | 7.25,41.81 C14.+ 7.62,41.85 7.62,41.87 7.19,41.87 6.01,40.7 6.01,37.77 6.52,37.27 6.52,32.19 7.53,31.17 9.11,31.17 9.13,31.19 | 9.13,31.19 9.14,31.21
N$25
  Top 0.406: C14.- 7.76,44.04 10.84,44 R4.2 10.84,43.87 11.09,43.49 13.38,45.77 R7.2
N$26
  Top 0.406: 4.49,37.14 4.46,37.16 R6.2 | R5.1 4.59,37.24 4.49,37.14 | 4.49,37.14 5.71,35.91 5.71,32.6 5.07,31.96 C15.-
N$28  (via drill 0.61, 0.71)
  Top 0.305: 3.94,17.49 3.94,17.36 v4.57,17.36
  Top 0.406: 4.32,34.13 R6.1 3.81,34.63 | 4.32,34.13 4.36,34.09 | 3.81,34.63 3.6,34.85 | 3.81,34.63 2.41,36.03 2.41,41.87 1.4,41.87 1.4,54.83 2.54,55.97 2.54,59.53 4.19,61.18 7.37,61.18 7.62,60.92 13.46,60.92 15.24,62.7 16.55,62.7 HEADPHONE.R | 3.81,34.63 | 3.94,17.49 3.94,26 4.67,26.73 C22.2 4.98,26.73 3.97,26.73 3.43,27.27 3.43,33.24 4.32,34.13 | R11.1 27.56,3.39 26.03,4.92 v25.91,4.92
  Bottom 0.305: 19.94,10.38 19.94,13.17 18.8,14.31 7.62,14.31 v4.57,17.36
  Bottom 0.406: 19.94,10.38 19.94,4.92 v25.91,4.92
N$29
  Top 0.406: U$4.9 9.19,35.04 9.19,35.11 10.2,35.11 11.06,35.97 C17.+ 10.81,38.38 10.84,38.79 10.83,39.05 C18.1
N$30
  Top 0.406: U$4.10 10.58,33.71 12.23,35.36 12.23,36.5 14.9,36.5 15.41,37.01 15.41,38.54 15.92,39.04 16.42,39.04 16.42,38.92 C19.1 15.92,38.79 15.92,41.71 C20.+
N$31
  Top 0.305: R13.2 29.84,10 24.89,10 23.88,8.98
  Top 0.406: U$9.P$3 22.23,6.7 23.62,8.09 C29.1 23.88,8.85 23.88,8.98 23.88,9.11
N$32
  Top 0.406: C24.1 25.31,12.75 R8.1
N$33
  Top 0.406: R8.2 25.09,17.84 22.39,17.84 | C23.1 22.39,17.84 | IC1.19 22.39,24.03 22.39,17.84
N$35
  Top 0.406: C25.1 17.02,3.14 16.89,3.27 | R15.1 14.2,5.96 16.89,3.27 | U$9.P$6 18.33,4.71 16.89,3.27
N$36
  Top 0.406: R16.2 18.67,8.6 19.58,7.69 U$9.P$4
N$37  (via drill 0.71)
  Top 0.406: C21.1 4.41,43.23 5.97,44.79 5.97,45.94 6.6,46.57 9.27,46.57 10.07,45.77 R7.1 10.81,47.61 v11.05,47.84 | C21.1 4.32,43.27 | 4.06,43.52 4.06,43.78 | 4.32,43.27 4.06,43.52 | 4.32,43.27 C21.1 | HEADPHONE.T 8.46,55.72 5.33,55.72 2.29,52.67 2.29,44.67 3.17,43.52 4.06,43.52 | v33.91,6.31 36.19,8.6 R12.1
  Bottom 0.305: 21.21,9.87 21.21,13.55 19.18,15.58 9.91,15.58 8.76,16.73 8.89,16.85
  Bottom 0.406: v11.05,47.84 11.05,38.57 8.89,36.41 8.89,16.85 | 21.21,9.87 21.21,8.09 22.99,6.31 v33.91,6.31
N$38
  Top 0.406: R19.2 31.27,8.5 31.24,8.47 31.69,8.03 | 31.69,8.03 32,7.71 C28.1 32.25,6.32 32.26,6.31 32.26,4.92 27.56,4.92 R11.2 | R12.2 32.26,8.6 31.69,8.03
N$39
  Top 0.406: R18.A 38.35,4.15 40.77,6.57 44.83,6.57 45.47,7.2 | C27.+ 45.64,7.28 45.59,7.33 45.47,7.2 | R14.1 11.3,8.47 9.78,6.95 9.78,4.41 12.95,1.23 46.35,1.23 47.62,2.5 47.62,5.04 45.47,7.2
N$40
  Top 0.406: R13.1 29.95,3.49 29.97,3.52 C28.2 32.76,3.52 35.56,6.31 37.72,6.31 38.23,6.82 R18.S
N$42
  Top 0.406: L3.1 23.32,4.71 U$9.P$1
N$43
  Top 0.406: U$3.P$2 54.07,42.89 54.1,42.89 54.1,53.45 U$3.P$0 54.23,53.72 54.23,56.61 51.31,61.56 47.52,65.34 S4.1 45.34,65.24 45.21,65.37 45.21,65.88 44.2,66.89 38.73,66.89 37.69,65.6 37.97,65.6 37.97,65.34 | 37.97,65.34 37.97,65.11 | S3.1 37.97,65.34
  Bottom 0.406: U$2.P$2 4.06,26.25 4.06,42.76 2.29,44.54 2.29,59.53 10.16,65.88 16.26,65.88 17.14,66.77 21.34,66.77 22.48,65.62 S2.1 22.45,65.39 22.48,65.37 23.88,66.77 29.08,66.77 30.23,65.62 S1.1 31.62,66.89 36.96,66.89 37.85,66 37.85,65.37 37.92,65.37 S3.1
RDY  (via drill 0.71)
  Top 0.305: IC4.22 25.78,49.27 25.78,49.24 v24.46,49.24
  Bottom 0.305: 24.26,49.24 | 24.26,49.24 24.3,49.2 | U$5.37 27.41,52.92 26.9,52.41 25.15,52.41 24.64,51.91 24.64,49.24 v24.46,49.24 24.26,49.24
RESET  (via drill 0.61)
  Top 0.305: IC4.24 22.87,46.69 22.48,47.08 22.48,51.4 v22.61,51.52
  Bottom 0.305: v22.61,51.52 22.61,52.54 22.41,52.73 | 22.41,52.73 22.35,52.8 | 22.41,52.73 22.35,52.67 22.33,52.69 U$5.41
RX  (via drill 0.61)
  Top 0.305: 20.19,63.34 v23.62,59.91 24,59.91 26.42,57.49 26.42,55.46 29.76,52.12
  Top 0.406: IC4.1 42.4,39.49 42.46,41.71 42.84,42.09 42.84,43.23 49.75,43.23 50.55,44.29 50.55,55.84 50.04,56.61 46.61,56.61 JP1.2 | 29.76,52.12 IC4.17 | S2.2 18.14,65.47 18.16,65.49 20.19,63.46 20.19,63.34
  Bottom 0.254: 46.23,64.73 45.08,63.97
  Bottom 0.305: 45.08,63.97 43.69,63.97 39.62,59.91 v23.62,59.91 | 46.23,64.73 47.12,64.73 48.13,63.72 48.13,62.07 46.99,60.92 46.99,60.16 46.61,59.78 JP1.2
S$1
  Top 0.406: 34.33,27.49 arc-166 34.33,29.52
STA_SCL
  Top 0.305: IC4.36 27.36,36.49 28.49,35.36 29,35.36 29.89,34.47 IC1.4
STA_SCLK
  Top 0.305: 21,36.88 21.63,36.25 25.44,36.25 27.35,34.34
  Top 0.406: IC4.32 21.61,40.29 21,39.68 21,36.88 | 27.35,34.34 IC1.6
STA_SDA
  Top 0.305: IC4.37 28.16,36.71 28.62,36.25 29.37,36.25 29.92,35.7 30.52,35.11 31.16,34.47 | IC1.3 31.16,34.34 31.36,34.64 32.96,36.24 35.43,36.24 35.99,35.62
  Top 0.406: 31.16,34.47 31.16,34.34 | 35.99,35.62 R9.1
STA_SDI
  Top 0.305: IC1.5 28.62,34.22 26.67,36.16 26.58,36.25
  Top 0.406: 26.67,36.16 26.56,36.27 IC4.35
TX
  Top 0.406: IC4.44 33.88,37.81 34.16,37.81 45.04,37.82 46.82,39.54 49.4,42.13 50.8,42.13 51.56,43.14 51.56,56.99 JP1.3 | 30.48,52.8 27.56,55.72 27.56,63.46 S1.2 | 30.48,52.8 30.61,52.67 | IC4.16 30.56,52.72 30.48,52.8
  Bottom 0.305: 49.15,59.53 JP1.3 49.15,63.72 47.37,65.49 46.86,65.49 45.85,66.64 44.32,66.64 43.31,65.49 43.31,64.99 41.66,63.34 41.66,62.83 39.37,60.54 30.35,60.54
  Bottom 0.406: 25.53,65.49 S1.2 30.35,60.67 30.35,60.54
VCC  (via drill 0.61, 0.71)
  Top 0.305: v24.55,35.23 24.81,34.73 | v18.58,52.38 19.22,53.01 22.61,53.01 23.41,53.01 v23.66,52.76 | IC4.28 29.63,43.49 30.39,44.25 36.11,44.25 36.11,44.29 | v18.41,12.79 17.43,13.77
  Top 0.406: IC1.23 27.25,24.16 | R2.2 14.62,16.92 14.67,16.92 15.54,17.79 C4.1 15.53,19.74 15.49,19.78 18.46,22.74 IC1.16 | IC1.23 27.35,22.79 28.24,21.9 28.24,20.12 29.25,19.11 29.76,19.11 | 29.76,19.11 C2.1 34.33,18.98 v36.74,21.39 36.74,32.63 33.7,32.63 IC1.1 | v29,14.66 28.74,14.66 26.71,16.69 21.38,16.69 21.12,15.8 18.08,15.8 | 29.76,19.11 30.52,19.11 v31.66,20.25 | IC1.23 27.45,24.16 27.47,24.19 27.5,24.16 IC1.24 | 24.81,34.73 IC1.8 | IC4.7 36.11,44.29 37.09,44.29 v37.25,43.87 | R17.2 44.36,45.52 46.14,47.3 D2.A | C8.+ 41.95,15.93 42.94,15.93 44.41,17.4 | 44.41,17.4 R3.2 | 47.12,26.71 47.12,26.63 | 47.12,26.71 U$1.6 | 47.12,26.71 47.12,27.91 45.22,29.81 45.21,29.81 45.21,34.12 | 42.54,19.36 D1.C 42.42,19.39 41.92,19.39 41.19,20.12 41.19,33.83 | 42.54,19.36 43.4,19.36 | 43.4,19.36 44.62,20.58 U$1.1 44.62,20.62 | 44.62,20.62 44.58,20.66 | U$1.2 44.64,20.6 44.62,20.62 | 42.54,19.36 42.54,19.39 | 42.54,19.36 42.54,19.27 | 45.08,36.41 44.96,36.29 44.98,36.26 C3.1 45.08,36.22 45.08,34.12 | R9.2 39.56,35.46 41.19,33.83 | 41.19,33.83 41.23,33.83 41.52,34.12 | 41.52,34.12 43.88,34.12 | R2.2 15.02,16.82 15.91,15.8 18.08,15.8 | L2.2 17.43,13.77 17.49,13.77 18.08,14.36 18.08,15.8 | 44.41,17.4 44.32,17.49 44.32,18.44 43.4,19.36 | IC1.14 17.19,34.55 17.78,35.14 18.67,35.14 19.81,36.29 19.77,36.32 C5.1 19.77,36.2 20.83,35.14 24.26,35.14 24.35,35.23 | 24.35,35.23 24.38,35.27 | v24.55,35.23 24.35,35.23 | 41.52,34.12 45.08,34.12 | 45.08,34.12 45.21,34.12 | 45.21,34.12 46.99,34.12 v46.99,34.89 | 45.21,34.12 45.21,34.13 | R2.2 13.61,17.35 v13.59,19.14 | 22.61,53.01 22.61,53.05 22.48,53.18 R20.2
  Bottom 0.305: U$5.32 33.76,52.89 33.03,52.15 32.89,52.02 32.89,46.62 32.87,46.6 | U$5.44 18.52,52.44 v18.58,52.38 | v23.66,52.76 23.92,52.67 23.88,52.67 24.38,53.18 26.16,53.18 | 26.16,53.18 26.2,53.18 | 26.16,53.18 U$5.38 26.67,55.48 | 26.67,55.48 U$5.13 | 26.67,55.48 26.67,55.46 | v18.41,12.79 18.41,10.63 18.16,10.38
  Bottom 0.406: 35.6,43.87 v37.25,43.87 | 35.6,43.87 29.89,38.16 29.89,33.58 30.78,32.69 38.52,32.69 40.98,35.06 | 40.98,35.06 45,38.92 45,39.08 | 45,39.08 45,45.01 D2.A | 34.2,45.2 34.27,45.2 35.6,43.87 | 34.2,45.2 29.57,45.2 27.35,47.43 23.79,47.43 22.77,48.44 22.77,49.97 23.88,51.07 23.88,52.67 v23.66,52.76 | 34.2,45.2 34.2,45.27 32.87,46.6 | 31.51,20.24 31.54,20.21 v31.66,20.25 31.62,20.25 | 38.71,18.26 36.7,18.26 36.7,21.39 v36.74,21.39 | 38.71,18.26 38.71,18.34 38.78,18.4 | D1.C 42.42,19.39 42.35,19.33 | 38.71,18.26 41.28,18.26 42.35,19.33 | 42.35,19.33 42.42,19.27 41.53,18.38 | 24.38,35.27 24.33,35.27 v24.55,35.23 24.3,35.14 10.41,35.14 10.03,34.76 10.03,19.9 10.79,19.14 11.16,19.13 12.31,19.13 v13.59,19.14 | 45,39.08 45.08,39.08 | 40.98,35.06 41.02,35.02 46.86,35.02 v46.99,34.89 | v29,14.66 29.07,14.61 | 29.07,14.61 29.25,14.48 29.21,14.06 29.5,13.77 32.3,13.77 32.26,18.25 31.62,18.25 31.62,20.25 | 31.62,20.25 31.62,20.28 | 28.96,14.44 29.07,14.56 29.07,14.61 | FM_SWITCH.P$2 5.84,8.47 7.49,10.12 17.91,10.12 18.16,10.38 | 33.03,52.15

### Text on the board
Bottom: ladyada@mit.edu | Minty MP3 v1.1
